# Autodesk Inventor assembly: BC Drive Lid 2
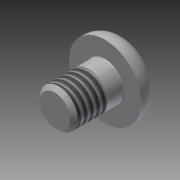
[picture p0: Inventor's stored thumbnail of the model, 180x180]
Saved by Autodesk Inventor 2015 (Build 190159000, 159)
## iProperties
Created: 2007-02
Part Number: BC Drive Lid 2
Document SubType Name: Assembly
Designer: Autodesk, Inc.
Mass: 1.89148 g
Surface Area: 2.92112 cm^2
Volume: 0.240646 cm^3
Density: 7.86 g/cm^3
ClientObjectVersion: 1
Author: Autodesk, Inc.
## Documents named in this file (2)
- C:\Users\Public\Documents\Autodesk\Inventor 2015\Samples\Models\Assemblies\Blower\Blower\Design Accelerator\BC Drive Lid 11.iam
- C:\Users\Public\Documents\Autodesk\Inventor 2015\Samples\Standard Parts\en-US\ANSI B18.3(03)\ANSI B18.3 - 10-32 UNF - UNF - 0.25(1).ipt
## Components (1 placed, 1 different names)
1. ANSI B18.3 - No. 10-32 - 1/4:1
